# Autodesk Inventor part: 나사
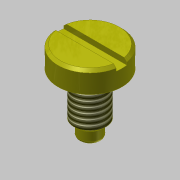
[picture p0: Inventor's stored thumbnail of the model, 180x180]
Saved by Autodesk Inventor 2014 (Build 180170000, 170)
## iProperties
Created: 2019-10
Part Number: 나사
Material: 스테인리스강
Document SubType Name: Modeling
Designer: mduedu
Density: 1 g/cm^3
Appearance: 노란색
Author: mduedu
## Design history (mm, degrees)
sketch "스케치1"
  geometry: L1 (0, 0)-(-6, 0); L2 (-6, 0)-(-6, -4); L3 (-6, -4)-(0, -4); L4 (0, -4)-(0, 0); L5 (0, -4)-(-3, -4); L6 (-3, -4)-(-3, -12.5); L7 (-3, -12.5)-(0, -12.5); L8 (0, -12.5)-(0, -4); L9 (0, -12.5)-(-2, -12.5); L10 (-2, -12.5)-(-2, -15); L11 (-2, -15)-(0, -15); L12 (0, -15)-(0, -12.5)
  constraints: 24 end point, 6 parallel, 3 horizontal, 3 perpendicular
  dimensions: "d0" = 15 distance between parallel lines of L11 L1; "d2" = 4 distance of L1.end L2.end; "d3" = 2.5 distance of L9.end L10.end; "d4" = 12 diameter of L2 L4; "d5" = 6 diameter of L6 L8; "d6" = 4 diameter of L10 L12
revolve "회전1" sketch "스케치1" stored, may be unused: angle "d7" = 90 deg
sketch "스케치2"
  geometry: L1 (2, -15)-(-2, -15) reference; L2 (-2, -15)-(-2, -12.5) reference; L3 (-2, -12.5)-(-3, -12.5) reference; L4 (-3, -12.5)-(-3, -4) reference; L5 (-3, -4)-(-6, -4) reference; L6 (-6, -4)-(-6, 0) reference; L7 (-6, 0)-(6, 0) reference; L8 (6, 0)-(6, -4) reference; L9 (6, -4)-(3, -4) reference; L10 (3, -4)-(3, -12.5) reference; L11 (3, -12.5)-(2, -12.5) reference; L12 (2, -12.5)-(2, -15) reference; L13 (0, 0)-(0, -15); L14 (-3, -4)-(-2.25, -4); L15 (-2.25, -4)-(-2.25, -4.5); L16 (-2.25, -4.5)-(-3, -4.5); L17 (-3, -4.5)-(-3, -4)
  constraints: 10 end point, 2 parallel, 1 horizontal, 1 midpoint, 1 perpendicular
  dimensions: "d8" = 4.5 diameter of L15 L13; "d10" = 0.5 distance between parallel lines of L16 L14
revolve "회전2" sketch "스케치2" stored, may be unused: angle "d11" = 90 deg
chamfer "모따기1" distance "d12" = 0.5; stored, may be unused: second distance "d13" = 2, angle "d14" = 45 deg
feature "스레드1" dims "d19" = 10, "d20" = 0
chamfer "모따기2" distance "d15" = 0.5; stored, may be unused: second distance "d16" = 2, angle "d17" = 45 deg
fillet "모깎기1" dims "d18" = 0.5
sketch "스케치3"
  geometry: L1 (-7.5, -1)-(7.5, -1); L2 (7.5, -1)-(7.5, 1); L3 (7.5, 1)-(-7.5, 1); L4 (-7.5, 1)-(-7.5, -1); L5 (-7.5, -1)-(7.5, 1); L6 (7.5, -1)-(-7.5, 1); 1 further point
  constraints: 12 end point, 2 midpoint, 2 parallel, 1 horizontal, 1 perpendicular
  dimensions: "d21" = 2 distance of L1.end L2.end; "d23" = 15 distance of L2.end L3.end
extrude "돌출1" cut sketch "스케치3" distance "d24" = 1; taper "d25" = 0 deg
node "솔리드1"
node "절단 모서리 투영1"
